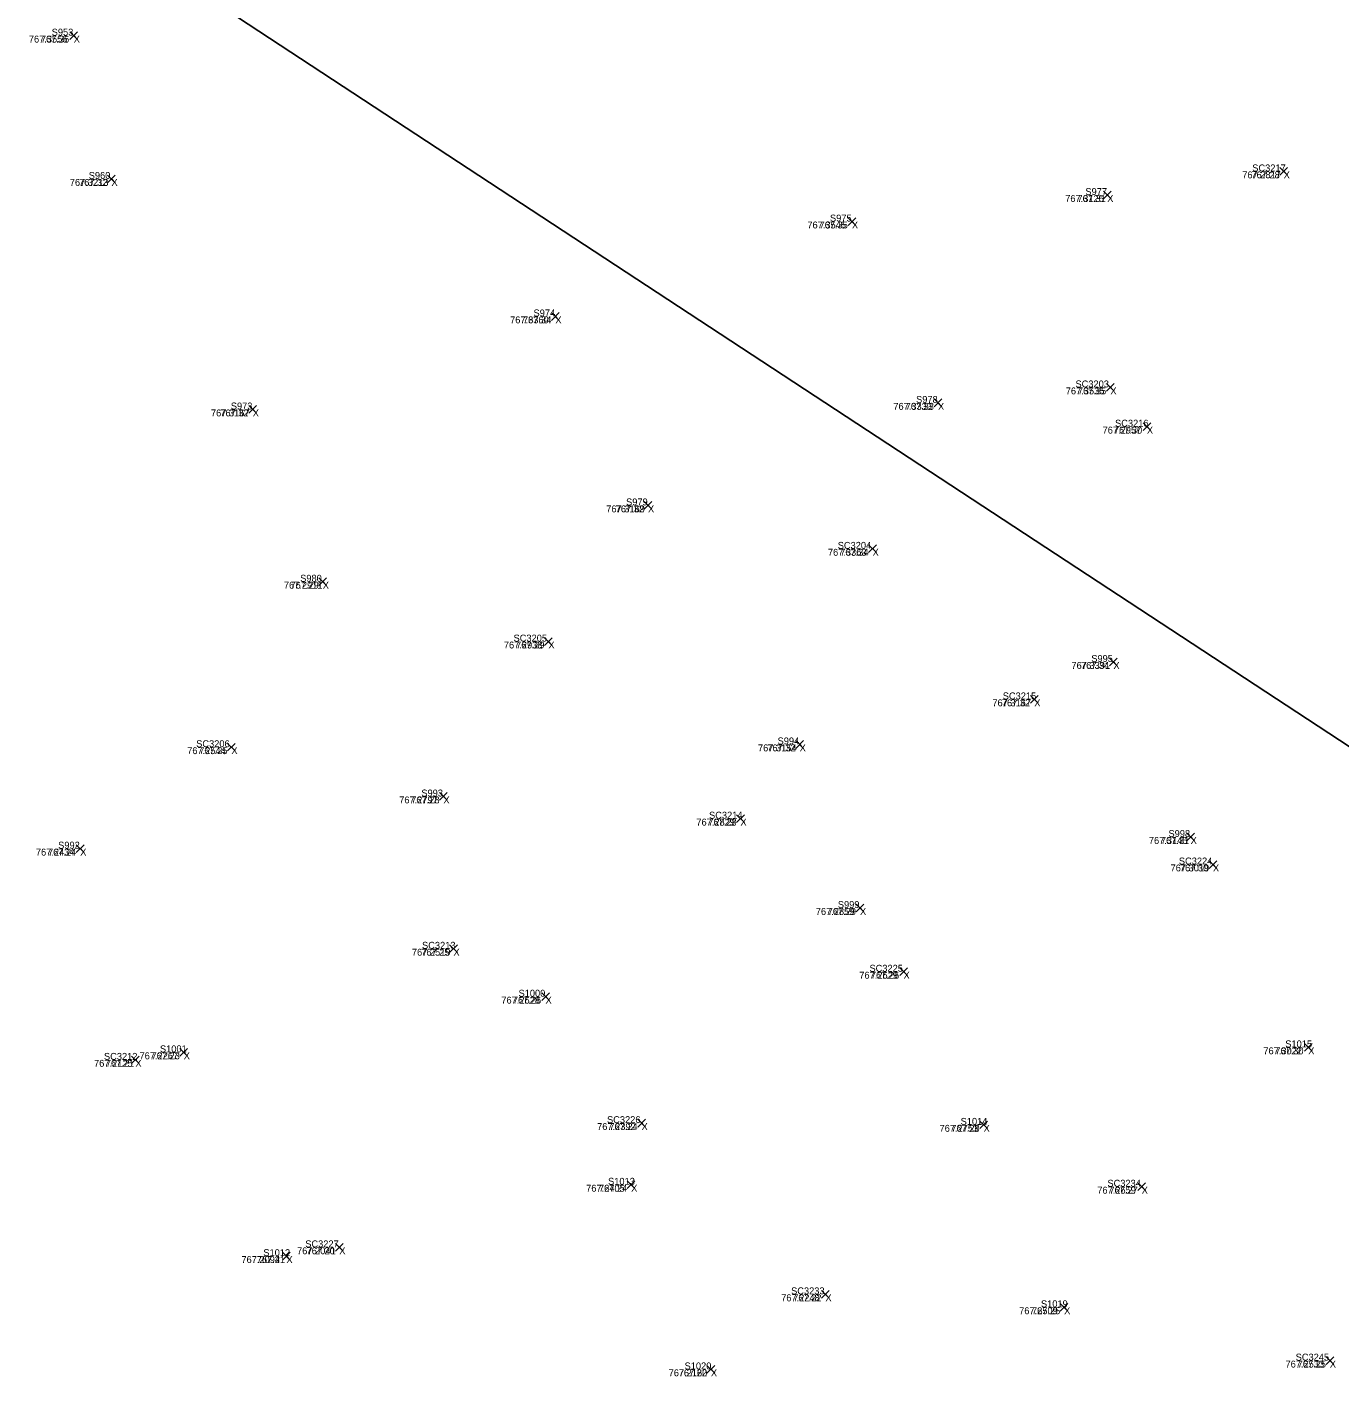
# Model space of a CAD drawing. Extents: x 1845019 to 1877956, y 680444 to 701081.
# Drawn here: x 1857703.38 to 1857714.75, y 694240.65 to 694252.54 of the extents above; entities that cross this region are included whole.
import ezdxf

# ---------------------------------------------------------------- set-up
doc = ezdxf.new("R2010")
doc.units = 0
for name, color, linetype in [('SV_X_CL_Survey_20', 7, 'Continuous'), ('SV_X_Random_Point', 7, 'Continuous'), ('SV_X_Text_Comment', 7, 'Continuous'), ('SV_X_Text_Elevation', 7, 'Continuous'), ('SV_X_Text_Name', 7, 'Continuous')]:
    doc.layers.add(name, color=color, linetype=linetype)

msp = doc.modelspace()

# ---------------------------------------------------------------- linework, layer by layer
at = {"layer": 'SV_X_CL_Survey_20'}
msp.add_line((1856038.267, 695346.314), (1858797.327, 693536.085), dxfattribs=at)
at = {"layer": 'SV_X_Random_Point'}
for p, q in [((1857703.745, 694252.439), (1857703.812, 694252.506)), ((1857703.745, 694252.506), (1857703.812, 694252.439)), ((1857703.745, 694252.439), (1857703.812, 694252.506)), ((1857703.745, 694252.506), (1857703.812, 694252.439)), ((1857714.23, 694251.264), (1857714.297, 694251.331)), ((1857714.23, 694251.331), (1857714.297, 694251.264)), ((1857714.23, 694251.264), (1857714.297, 694251.331)), ((1857714.23, 694251.331), (1857714.297, 694251.264)), ((1857704.072, 694251.199), (1857704.139, 694251.265)), ((1857704.072, 694251.265), (1857704.139, 694251.199)), ((1857704.072, 694251.199), (1857704.139, 694251.265)), ((1857704.072, 694251.265), (1857704.139, 694251.199)), ((1857712.701, 694251.059), (1857712.768, 694251.125)), ((1857712.701, 694251.125), (1857712.768, 694251.059)), ((1857712.701, 694251.059), (1857712.768, 694251.125)), ((1857712.701, 694251.125), (1857712.768, 694251.059)), ((1857710.489, 694250.829), (1857710.555, 694250.896)), ((1857710.489, 694250.896), (1857710.555, 694250.829)), ((1857710.489, 694250.829), (1857710.555, 694250.896)), ((1857710.489, 694250.896), (1857710.555, 694250.829)), ((1857707.919, 694250.007), (1857707.986, 694250.074)), ((1857707.919, 694250.074), (1857707.986, 694250.007)), ((1857707.919, 694250.007), (1857707.986, 694250.074)), ((1857707.919, 694250.074), (1857707.986, 694250.007)), ((1857712.728, 694249.393), (1857712.795, 694249.459)), ((1857712.728, 694249.459), (1857712.795, 694249.393)), ((1857712.728, 694249.393), (1857712.795, 694249.459)), ((1857712.728, 694249.459), (1857712.795, 694249.393)), ((1857711.235, 694249.259), (1857711.301, 694249.326)), ((1857711.235, 694249.326), (1857711.301, 694249.259)), ((1857711.235, 694249.259), (1857711.301, 694249.326)), ((1857711.235, 694249.326), (1857711.301, 694249.259)), ((1857705.297, 694249.202), (1857705.363, 694249.269)), ((1857705.297, 694249.269), (1857705.363, 694249.202)), ((1857705.297, 694249.202), (1857705.363, 694249.269)), ((1857705.297, 694249.269), (1857705.363, 694249.202)), ((1857713.045, 694249.053), (1857713.112, 694249.12)), ((1857713.045, 694249.12), (1857713.112, 694249.053)), ((1857713.045, 694249.053), (1857713.112, 694249.12)), ((1857713.045, 694249.12), (1857713.112, 694249.053)), ((1857708.722, 694248.371), (1857708.789, 694248.438)), ((1857708.722, 694248.438), (1857708.789, 694248.371)), ((1857708.722, 694248.371), (1857708.789, 694248.438)), ((1857708.722, 694248.438), (1857708.789, 694248.371)), ((1857710.667, 694247.995), (1857710.734, 694248.062)), ((1857710.667, 694248.062), (1857710.734, 694247.995)), ((1857710.667, 694247.995), (1857710.734, 694248.062)), ((1857710.667, 694248.062), (1857710.734, 694247.995)), ((1857705.903, 694247.709), (1857705.97, 694247.776)), ((1857705.903, 694247.776), (1857705.97, 694247.709)), ((1857705.903, 694247.709), (1857705.97, 694247.776)), ((1857705.903, 694247.776), (1857705.97, 694247.709)), ((1857707.858, 694247.191), (1857707.925, 694247.258)), ((1857707.858, 694247.258), (1857707.925, 694247.191)), ((1857707.858, 694247.191), (1857707.925, 694247.258)), ((1857707.858, 694247.258), (1857707.925, 694247.191)), ((1857712.754, 694247.015), (1857712.821, 694247.082)), ((1857712.754, 694247.082), (1857712.821, 694247.015)), ((1857712.754, 694247.015), (1857712.821, 694247.082)), ((1857712.754, 694247.082), (1857712.821, 694247.015)), ((1857712.068, 694246.691), (1857712.135, 694246.757)), ((1857712.068, 694246.757), (1857712.135, 694246.691)), ((1857712.068, 694246.691), (1857712.135, 694246.757)), ((1857712.068, 694246.757), (1857712.135, 694246.691)), ((1857705.112, 694246.277), (1857705.179, 694246.343)), ((1857705.112, 694246.343), (1857705.179, 694246.277)), ((1857705.112, 694246.277), (1857705.179, 694246.343)), ((1857705.112, 694246.343), (1857705.179, 694246.277)), ((1857710.036, 694246.3), (1857710.102, 694246.367)), ((1857710.036, 694246.367), (1857710.102, 694246.3)), ((1857710.036, 694246.3), (1857710.102, 694246.367)), ((1857710.036, 694246.367), (1857710.102, 694246.3)), ((1857706.949, 694245.85), (1857707.016, 694245.917)), ((1857706.949, 694245.917), (1857707.016, 694245.85)), ((1857706.949, 694245.85), (1857707.016, 694245.917)), ((1857706.949, 694245.917), (1857707.016, 694245.85)), ((1857709.523, 694245.658), (1857709.59, 694245.725)), ((1857709.523, 694245.725), (1857709.59, 694245.658)), ((1857709.523, 694245.658), (1857709.59, 694245.725)), ((1857709.523, 694245.725), (1857709.59, 694245.658)), ((1857713.424, 694245.498), (1857713.491, 694245.565)), ((1857713.424, 694245.565), (1857713.491, 694245.498)), ((1857713.424, 694245.498), (1857713.491, 694245.565)), ((1857713.424, 694245.565), (1857713.491, 694245.498)), ((1857703.801, 694245.397), (1857703.868, 694245.464)), ((1857703.801, 694245.464), (1857703.868, 694245.397)), ((1857703.801, 694245.397), (1857703.868, 694245.464)), ((1857703.801, 694245.464), (1857703.868, 694245.397)), ((1857713.617, 694245.26), (1857713.684, 694245.327)), ((1857713.617, 694245.327), (1857713.684, 694245.26)), ((1857713.617, 694245.26), (1857713.684, 694245.327)), ((1857713.617, 694245.327), (1857713.684, 694245.26)), ((1857710.559, 694244.883), (1857710.625, 694244.95)), ((1857710.559, 694244.95), (1857710.625, 694244.883)), ((1857710.559, 694244.883), (1857710.625, 694244.95)), ((1857710.559, 694244.95), (1857710.625, 694244.883)), ((1857707.036, 694244.531), (1857707.103, 694244.598)), ((1857707.036, 694244.598), (1857707.103, 694244.531)), ((1857707.036, 694244.531), (1857707.103, 694244.598)), ((1857707.036, 694244.598), (1857707.103, 694244.531)), ((1857710.936, 694244.332), (1857711.003, 694244.398)), ((1857710.936, 694244.398), (1857711.003, 694244.332)), ((1857710.936, 694244.332), (1857711.003, 694244.398)), ((1857710.936, 694244.398), (1857711.003, 694244.332)), ((1857707.834, 694244.115), (1857707.901, 694244.182)), ((1857707.834, 694244.182), (1857707.901, 694244.115)), ((1857707.834, 694244.115), (1857707.901, 694244.182)), ((1857707.834, 694244.182), (1857707.901, 694244.115)), ((1857704.699, 694243.633), (1857704.765, 694243.7)), ((1857704.699, 694243.7), (1857704.765, 694243.633)), ((1857704.699, 694243.633), (1857704.765, 694243.7)), ((1857704.699, 694243.7), (1857704.765, 694243.633)), ((1857714.443, 694243.677), (1857714.51, 694243.744)), ((1857714.443, 694243.744), (1857714.51, 694243.677)), ((1857714.443, 694243.677), (1857714.51, 694243.744)), ((1857714.443, 694243.744), (1857714.51, 694243.677)), ((1857704.28, 694243.569), (1857704.347, 694243.635)), ((1857704.28, 694243.635), (1857704.347, 694243.569)), ((1857704.28, 694243.569), (1857704.347, 694243.635)), ((1857704.28, 694243.635), (1857704.347, 694243.569)), ((1857708.666, 694243.02), (1857708.732, 694243.087)), ((1857708.666, 694243.087), (1857708.732, 694243.02)), ((1857708.666, 694243.02), (1857708.732, 694243.087)), ((1857708.666, 694243.087), (1857708.732, 694243.02)), ((1857711.63, 694243.006), (1857711.696, 694243.072)), ((1857711.63, 694243.072), (1857711.696, 694243.006)), ((1857711.63, 694243.006), (1857711.696, 694243.072)), ((1857711.63, 694243.072), (1857711.696, 694243.006)), ((1857708.575, 694242.487), (1857708.642, 694242.554)), ((1857708.575, 694242.554), (1857708.642, 694242.487)), ((1857708.575, 694242.487), (1857708.642, 694242.554)), ((1857708.575, 694242.554), (1857708.642, 694242.487)), ((1857712.999, 694242.47), (1857713.066, 694242.536)), ((1857712.999, 694242.536), (1857713.066, 694242.47)), ((1857712.999, 694242.47), (1857713.066, 694242.536)), ((1857712.999, 694242.536), (1857713.066, 694242.47)), ((1857705.588, 694241.868), (1857705.655, 694241.935)), ((1857705.588, 694241.935), (1857705.655, 694241.868)), ((1857705.588, 694241.868), (1857705.655, 694241.935)), ((1857705.588, 694241.935), (1857705.655, 694241.868)), ((1857706.047, 694241.945), (1857706.114, 694242.011)), ((1857706.047, 694242.011), (1857706.114, 694241.945)), ((1857706.047, 694241.945), (1857706.114, 694242.011)), ((1857706.047, 694242.011), (1857706.114, 694241.945)), ((1857710.259, 694241.537), (1857710.325, 694241.604)), ((1857710.259, 694241.604), (1857710.325, 694241.537)), ((1857710.259, 694241.537), (1857710.325, 694241.604)), ((1857710.259, 694241.604), (1857710.325, 694241.537)), ((1857712.327, 694241.426), (1857712.394, 694241.492)), ((1857712.327, 694241.492), (1857712.394, 694241.426)), ((1857712.327, 694241.426), (1857712.394, 694241.492)), ((1857712.327, 694241.492), (1857712.394, 694241.426)), ((1857709.266, 694240.888), (1857709.333, 694240.954)), ((1857709.266, 694240.954), (1857709.333, 694240.888)), ((1857709.266, 694240.888), (1857709.333, 694240.954)), ((1857709.266, 694240.954), (1857709.333, 694240.888)), ((1857714.63, 694240.963), (1857714.697, 694241.03)), ((1857714.63, 694241.03), (1857714.697, 694240.963)), ((1857714.63, 694240.963), (1857714.697, 694241.03)), ((1857714.63, 694241.03), (1857714.697, 694240.963))]:
    msp.add_line(p, q, dxfattribs=at)

# ---------------------------------------------------------------- texts
at = {"layer": 'SV_X_Text_Comment'}
for p in [(1857703.779, 694252.413), (1857714.263, 694251.237), (1857704.106, 694251.172), (1857712.734, 694251.032), (1857710.522, 694250.803), (1857707.952, 694249.981), (1857712.761, 694249.366), (1857711.268, 694249.232), (1857705.33, 694249.175), (1857713.078, 694249.026), (1857708.755, 694248.344), (1857710.701, 694247.968), (1857705.937, 694247.683), (1857707.892, 694247.165), (1857712.788, 694246.988), (1857712.102, 694246.664), (1857705.145, 694246.25), (1857710.069, 694246.274), (1857706.982, 694245.823), (1857709.556, 694245.631), (1857713.457, 694245.472), (1857703.835, 694245.371), (1857713.65, 694245.234), (1857710.592, 694244.857), (1857707.069, 694244.504), (1857710.969, 694244.305), (1857707.867, 694244.089), (1857714.476, 694243.65), (1857704.313, 694243.542), (1857704.732, 694243.607), (1857708.699, 694242.994), (1857711.663, 694242.979), (1857708.609, 694242.46), (1857713.033, 694242.443), (1857705.622, 694241.842), (1857706.08, 694241.918), (1857710.292, 694241.511), (1857712.361, 694241.399), (1857714.663, 694240.937), (1857709.3, 694240.861)]:
    msp.add_text('X', height=0.06, dxfattribs=at).set_placement(p)
at = {"layer": 'SV_X_Text_Elevation'}
for s, p in [('767.3556', (1857703.39, 694252.413)), ('767.36', (1857703.494, 694252.413)), ('767.2817', (1857713.904, 694251.237)), ('767.28', (1857713.984, 694251.237)), ('767.3213', (1857703.745, 694251.172)), ('767.32', (1857703.825, 694251.172)), ('767.3126', (1857712.37, 694251.032)), ('767.31', (1857712.476, 694251.032)), ('767.3545', (1857710.136, 694250.803)), ('767.35', (1857710.241, 694250.803)), ('767.3360', (1857707.56, 694249.981)), ('767.34', (1857707.672, 694249.981)), ('767.3535', (1857712.375, 694249.366)), ('767.35', (1857712.48, 694249.366)), ('767.3333', (1857710.881, 694249.232)), ('767.33', (1857710.987, 694249.232)), ('767.3167', (1857704.968, 694249.175)), ('767.32', (1857705.049, 694249.175)), ('767.2957', (1857712.694, 694249.026)), ('767.30', (1857712.792, 694249.026)), ('767.3169', (1857708.393, 694248.344)), ('767.32', (1857708.475, 694248.344)), ('767.3363', (1857710.314, 694247.968)), ('767.34', (1857710.42, 694247.968)), ('767.2911', (1857705.6, 694247.683)), ('767.29', (1857705.657, 694247.683)), ('767.2938', (1857707.506, 694247.165)), ('767.29', (1857707.612, 694247.165)), ('767.3391', (1857712.424, 694246.988)), ('767.34', (1857712.507, 694246.988)), ('767.3167', (1857711.739, 694246.664)), ('767.32', (1857711.821, 694246.664)), ('767.2544', (1857704.762, 694246.25)), ('767.25', (1857704.866, 694246.25)), ('767.3154', (1857709.708, 694246.274)), ('767.32', (1857709.788, 694246.274)), ('767.2797', (1857706.599, 694245.823)), ('767.28', (1857706.703, 694245.823)), ('767.2829', (1857709.174, 694245.631)), ('767.28', (1857709.277, 694245.631)), ('767.3145', (1857713.095, 694245.472)), ('767.31', (1857713.199, 694245.472)), ('767.2434', (1857703.451, 694245.371)), ('767.24', (1857703.556, 694245.371)), ('767.3019', (1857713.283, 694245.234)), ('767.30', (1857713.364, 694245.234)), ('767.2859', (1857710.209, 694244.857)), ('767.29', (1857710.312, 694244.857)), ('767.2519', (1857706.709, 694244.504)), ('767.25', (1857706.79, 694244.504)), ('767.2629', (1857710.586, 694244.305)), ('767.26', (1857710.686, 694244.305)), ('767.2628', (1857707.484, 694244.089)), ('767.26', (1857707.584, 694244.089)), ('767.3022', (1857714.087, 694243.65)), ('767.30', (1857714.19, 694243.65)), ('767.2125', (1857703.955, 694243.542)), ('767.21', (1857704.057, 694243.542)), ('767.2267', (1857704.349, 694243.607)), ('767.23', (1857704.453, 694243.607)), ('767.2392', (1857708.314, 694242.994)), ('767.24', (1857708.42, 694242.994)), ('767.2753', (1857711.281, 694242.979)), ('767.28', (1857711.383, 694242.979)), ('767.2405', (1857708.219, 694242.46)), ('767.24', (1857708.33, 694242.46)), ('767.2659', (1857712.648, 694242.443)), ('767.27', (1857712.753, 694242.443)), ('767.2094', (1857705.232, 694241.842)), ('767.21', (1857705.365, 694241.842)), ('767.2041', (1857705.714, 694241.918)), ('767.20', (1857705.796, 694241.918)), ('767.2248', (1857709.909, 694241.511)), ('767.22', (1857710.013, 694241.511)), ('767.2509', (1857711.971, 694241.399)), ('767.25', (1857712.082, 694241.399)), ('767.2533', (1857714.279, 694240.937)), ('767.25', (1857714.384, 694240.937)), ('767.2160', (1857708.934, 694240.861)), ('767.22', (1857709.021, 694240.861))]:
    msp.add_text(s, height=0.06, dxfattribs=at).set_placement(p)
at = {"layer": 'SV_X_Text_Name'}
for s, p in [('S953', (1857703.588, 694252.473)), ('S953', (1857703.588, 694252.473)), ('S960', (1857703.909, 694251.232)), ('S960', (1857703.909, 694251.232)), ('SC3217', (1857713.991, 694251.297)), ('SC3217', (1857713.991, 694251.297)), ('S977', (1857712.545, 694251.092)), ('S977', (1857712.545, 694251.092)), ('S975', (1857710.332, 694250.863)), ('S975', (1857710.332, 694250.863)), ('S974', (1857707.763, 694250.041)), ('S974', (1857707.763, 694250.041)), ('SC3203', (1857712.459, 694249.426)), ('SC3203', (1857712.459, 694249.426)), ('S973', (1857705.14, 694249.235)), ('S973', (1857705.14, 694249.235)), ('S978', (1857711.078, 694249.292)), ('S978', (1857711.078, 694249.292)), ('SC3216', (1857712.802, 694249.086)), ('SC3216', (1857712.802, 694249.086)), ('S979', (1857708.565, 694248.404)), ('S979', (1857708.565, 694248.404)), ('SC3204', (1857710.399, 694248.028)), ('SC3204', (1857710.399, 694248.028)), ('S980', (1857705.741, 694247.743)), ('S980', (1857705.741, 694247.743)), ('SC3205', (1857707.59, 694247.225)), ('SC3205', (1857707.59, 694247.225)), ('S995', (1857712.596, 694247.048)), ('S995', (1857712.596, 694247.048)), ('SC3215', (1857711.829, 694246.724)), ('SC3215', (1857711.829, 694246.724)), ('SC3206', (1857704.84, 694246.31)), ('SC3206', (1857704.84, 694246.31)), ('S994', (1857709.878, 694246.334)), ('S994', (1857709.878, 694246.334)), ('S993', (1857706.791, 694245.883)), ('S993', (1857706.791, 694245.883)), ('SC3214', (1857709.284, 694245.691)), ('SC3214', (1857709.284, 694245.691)), ('S998', (1857713.265, 694245.532)), ('S998', (1857713.265, 694245.532)), ('S992', (1857703.644, 694245.431)), ('S992', (1857703.644, 694245.431)), ('SC3224', (1857713.355, 694245.294)), ('SC3224', (1857713.355, 694245.294)), ('S999', (1857710.4, 694244.917)), ('S999', (1857710.4, 694244.917)), ('SC3213', (1857706.797, 694244.564)), ('SC3213', (1857706.797, 694244.564)), ('SC3225', (1857710.674, 694244.365)), ('SC3225', (1857710.674, 694244.365)), ('S1000', (1857707.633, 694244.149)), ('S1000', (1857707.633, 694244.149)), ('S1001', (1857704.526, 694243.667)), ('S1001', (1857704.526, 694243.667)), ('S1015', (1857714.277, 694243.71)), ('S1015', (1857714.277, 694243.71)), ('SC3212', (1857704.041, 694243.602)), ('SC3212', (1857704.041, 694243.602)), ('SC3226', (1857708.4, 694243.054)), ('SC3226', (1857708.4, 694243.054)), ('S1014', (1857711.464, 694243.039)), ('S1014', (1857711.464, 694243.039)), ('S1013', (1857708.409, 694242.52)), ('S1013', (1857708.409, 694242.52)), ('SC3234', (1857712.736, 694242.503)), ('SC3234', (1857712.736, 694242.503)), ('SC3227', (1857705.785, 694241.978)), ('SC3227', (1857705.785, 694241.978)), ('S1012', (1857705.422, 694241.902)), ('S1012', (1857705.422, 694241.902)), ('SC3233', (1857709.995, 694241.571)), ('SC3233', (1857709.995, 694241.571)), ('S1019', (1857712.16, 694241.459)), ('S1019', (1857712.16, 694241.459)), ('S1020', (1857709.072, 694240.921)), ('S1020', (1857709.072, 694240.921)), ('SC3245', (1857714.367, 694240.997)), ('SC3245', (1857714.367, 694240.997))]:
    msp.add_text(s, height=0.06, dxfattribs=at).set_placement(p)

doc.saveas('drawing.dxf')
